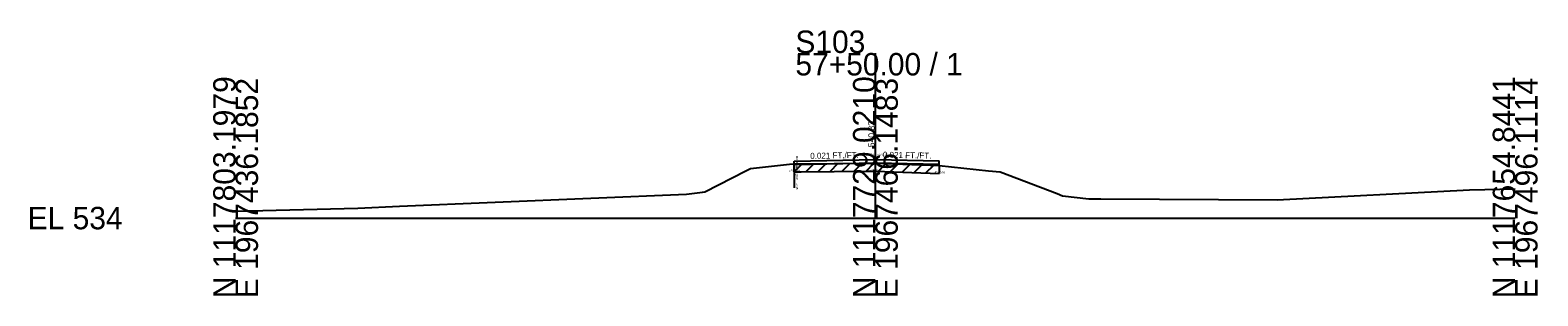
# Model space of a CAD drawing. Extents: x -26 to 163, y -10 to 24018.
# Drawn here: x -25.7 to 162.8, y 6990.3 to 7023.4 of the extents above; entities that cross this region are included whole.
import ezdxf

# ---------------------------------------------------------------- set-up
doc = ezdxf.new("R2010")
doc.units = 0
for name, color, linetype in [('RD_GPK_XS_Cell', 7, 'Continuous'), ('RD_XS_ExGround', 7, 'Continuous'), ('RD_XS_ExPaveRet', 7, 'Continuous'), ('RD_XS_Misc_Line', 7, 'Continuous'), ('RD_XS_PaveOvlay_CP', 7, 'Continuous'), ('RD_XS_TX_Elev_EX', 7, 'Continuous'), ('RD_XS_TX_ExEOP', 7, 'Continuous'), ('RD_XS_TX_Notes', 7, 'Continuous'), ('RD_XS_TX_Profile', 7, 'Continuous'), ('RD_XS_TX_Slope', 7, 'Continuous')]:
    doc.layers.add(name, color=color, linetype=linetype)

msp = doc.modelspace()

# ---------------------------------------------------------------- linework, layer by layer
at = {"layer": 'RD_GPK_XS_Cell'}
for p, q in [((80, 7000), (80, 7020.59)), ((0, 7000), (80, 7000)), ((80, 7000), (160, 7000))]:
    msp.add_line(p, q, dxfattribs=at)
at = {"layer": 'RD_XS_ExGround'}
msp.add_lwpolyline([(0, 7000.86), (15.28, 7001.25), (20.48, 7001.47), (56.38, 7002.97), (58.37, 7003.23), (58.68, 7003.26), (63.81, 7005.89), (64.39, 7006.18), (69.28, 7006.71), (69.83, 7006.77), (70.71, 7006.78), (78.97, 7006.86), (80, 7006.83), (87.96, 7006.57), (94.15, 7005.91), (95.61, 7005.75), (102.72, 7003.05), (103.4, 7002.79), (106.69, 7002.39), (108.19, 7002.38), (130.23, 7002.29), (154.31, 7003.52), (160, 7003.66)], dxfattribs=at)
at = {"layer": 'RD_XS_ExPaveRet'}
for p, q in [((69.83, 7005.77), (70.84, 7006.78)), ((69.83, 7005.77), (69.83, 7006.77)), ((71.33, 7005.79), (72.34, 7006.8)), ((72.83, 7005.8), (73.84, 7006.81)), ((74.33, 7005.82), (75.34, 7006.83)), ((75.83, 7005.83), (76.84, 7006.84)), ((77.33, 7005.85), (78.34, 7006.86)), ((78.83, 7005.86), (79.81, 7006.84)), ((80.33, 7005.82), (81.3, 7006.79)), ((81.83, 7005.77), (82.8, 7006.74)), ((83.33, 7005.72), (84.3, 7006.69)), ((84.83, 7005.68), (85.8, 7006.64)), ((86.33, 7005.63), (87.3, 7006.59)), ((87.96, 7006.57), (87.96, 7005.57)), ((69.83, 7005.77), (70.71, 7005.78)), ((70.71, 7005.78), (78.97, 7005.86)), ((78.97, 7005.86), (80, 7005.83)), ((80, 7005.83), (87.96, 7005.57))]:
    msp.add_line(p, q, dxfattribs=at)
at = {"layer": 'RD_XS_Misc_Line'}
msp.add_line((69.83, 7006.77), (69.83, 7003.77), dxfattribs=at)
at = {"layer": 'RD_XS_PaveOvlay_CP'}
for p, q in [((69.83, 7007.09), (80, 7007.3)), ((69.83, 7006.77), (69.83, 7007.09)), ((80, 7006.83), (69.83, 7006.62)), ((80, 7007.3), (87.96, 7007.14)), ((87.96, 7006.67), (80, 7006.83)), ((87.96, 7006.57), (87.96, 7007.14))]:
    msp.add_line(p, q, dxfattribs=at)

# ---------------------------------------------------------------- texts
at = {"layer": 'RD_GPK_XS_Cell'}
for s, p in [('S103', (70, 7020.59)), ('57+50.00 / 1', (70, 7017.79)), ('EL 534', (-26, 6998.6))]:
    msp.add_text(s, height=2.8, dxfattribs=at).set_placement(p)
for s, p in [('N 1117803.1979', (0, 6990)), ('E 1967436.1852', (2.8, 6990)), ('N 1117729.0210', (80, 6990)), ('E 1967466.1483', (82.8, 6990)), ('N 1117654.8441', (160, 6990)), ('E 1967496.1114', (162.8, 6990))]:
    msp.add_text(s, height=2.8, rotation=90, dxfattribs=at).set_placement(p)
at = {"layer": 'RD_XS_TX_Elev_EX'}
msp.add_text('540.83', height=0.8, rotation=90, dxfattribs=at).set_placement((79.9, 7008.83))
at = {"layer": 'RD_XS_TX_ExEOP'}
for s, p in [('EOP-L', (69.78, 7007.09)), ('EOP-R', (87.91, 7007.14))]:
    msp.add_text(s, height=0.1, rotation=270, dxfattribs=at).set_placement(p)
at = {"layer": 'RD_XS_TX_Notes'}
for s, p in [('Elev. @CL = 541.30', (78.47, 7007.8)), (' dE= 0.32', (69.12, 7005.77)), (' dE= 0.47', (79.29, 7005.83)), (' dE= 0.56', (87.24, 7005.57))]:
    msp.add_text(s, height=0.25, dxfattribs=at).set_placement(p)
msp.add_text(' Min. Distance @CP = -0.15', height=0.25, rotation=270, dxfattribs=at).set_placement((70.08, 7007.86))
at = {"layer": 'RD_XS_TX_Profile'}
msp.add_text('CL', height=0.25, dxfattribs=at).set_placement((79.77, 7007.3))
at = {"layer": 'RD_XS_TX_Slope'}
for rotation, p in [(1.1916, (71.86, 7007.38)), (358.8084, (80.93, 7007.53))]:
    msp.add_text('0.021 FT./FT.', height=0.75, rotation=rotation, dxfattribs=at).set_placement(p)

doc.saveas('drawing.dxf')
